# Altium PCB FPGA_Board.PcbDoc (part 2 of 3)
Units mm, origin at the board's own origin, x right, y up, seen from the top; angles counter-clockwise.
Board outline 130 x 90 mm, 4 copper layers (Component Side, Signal Layer 1, Signal Layer 2, Bottom Layer), stack 0.651 mm thick; 303 components, 175 nets, 968 pads, 775 vias.
Unrouted connection lines stored in the file: 193.
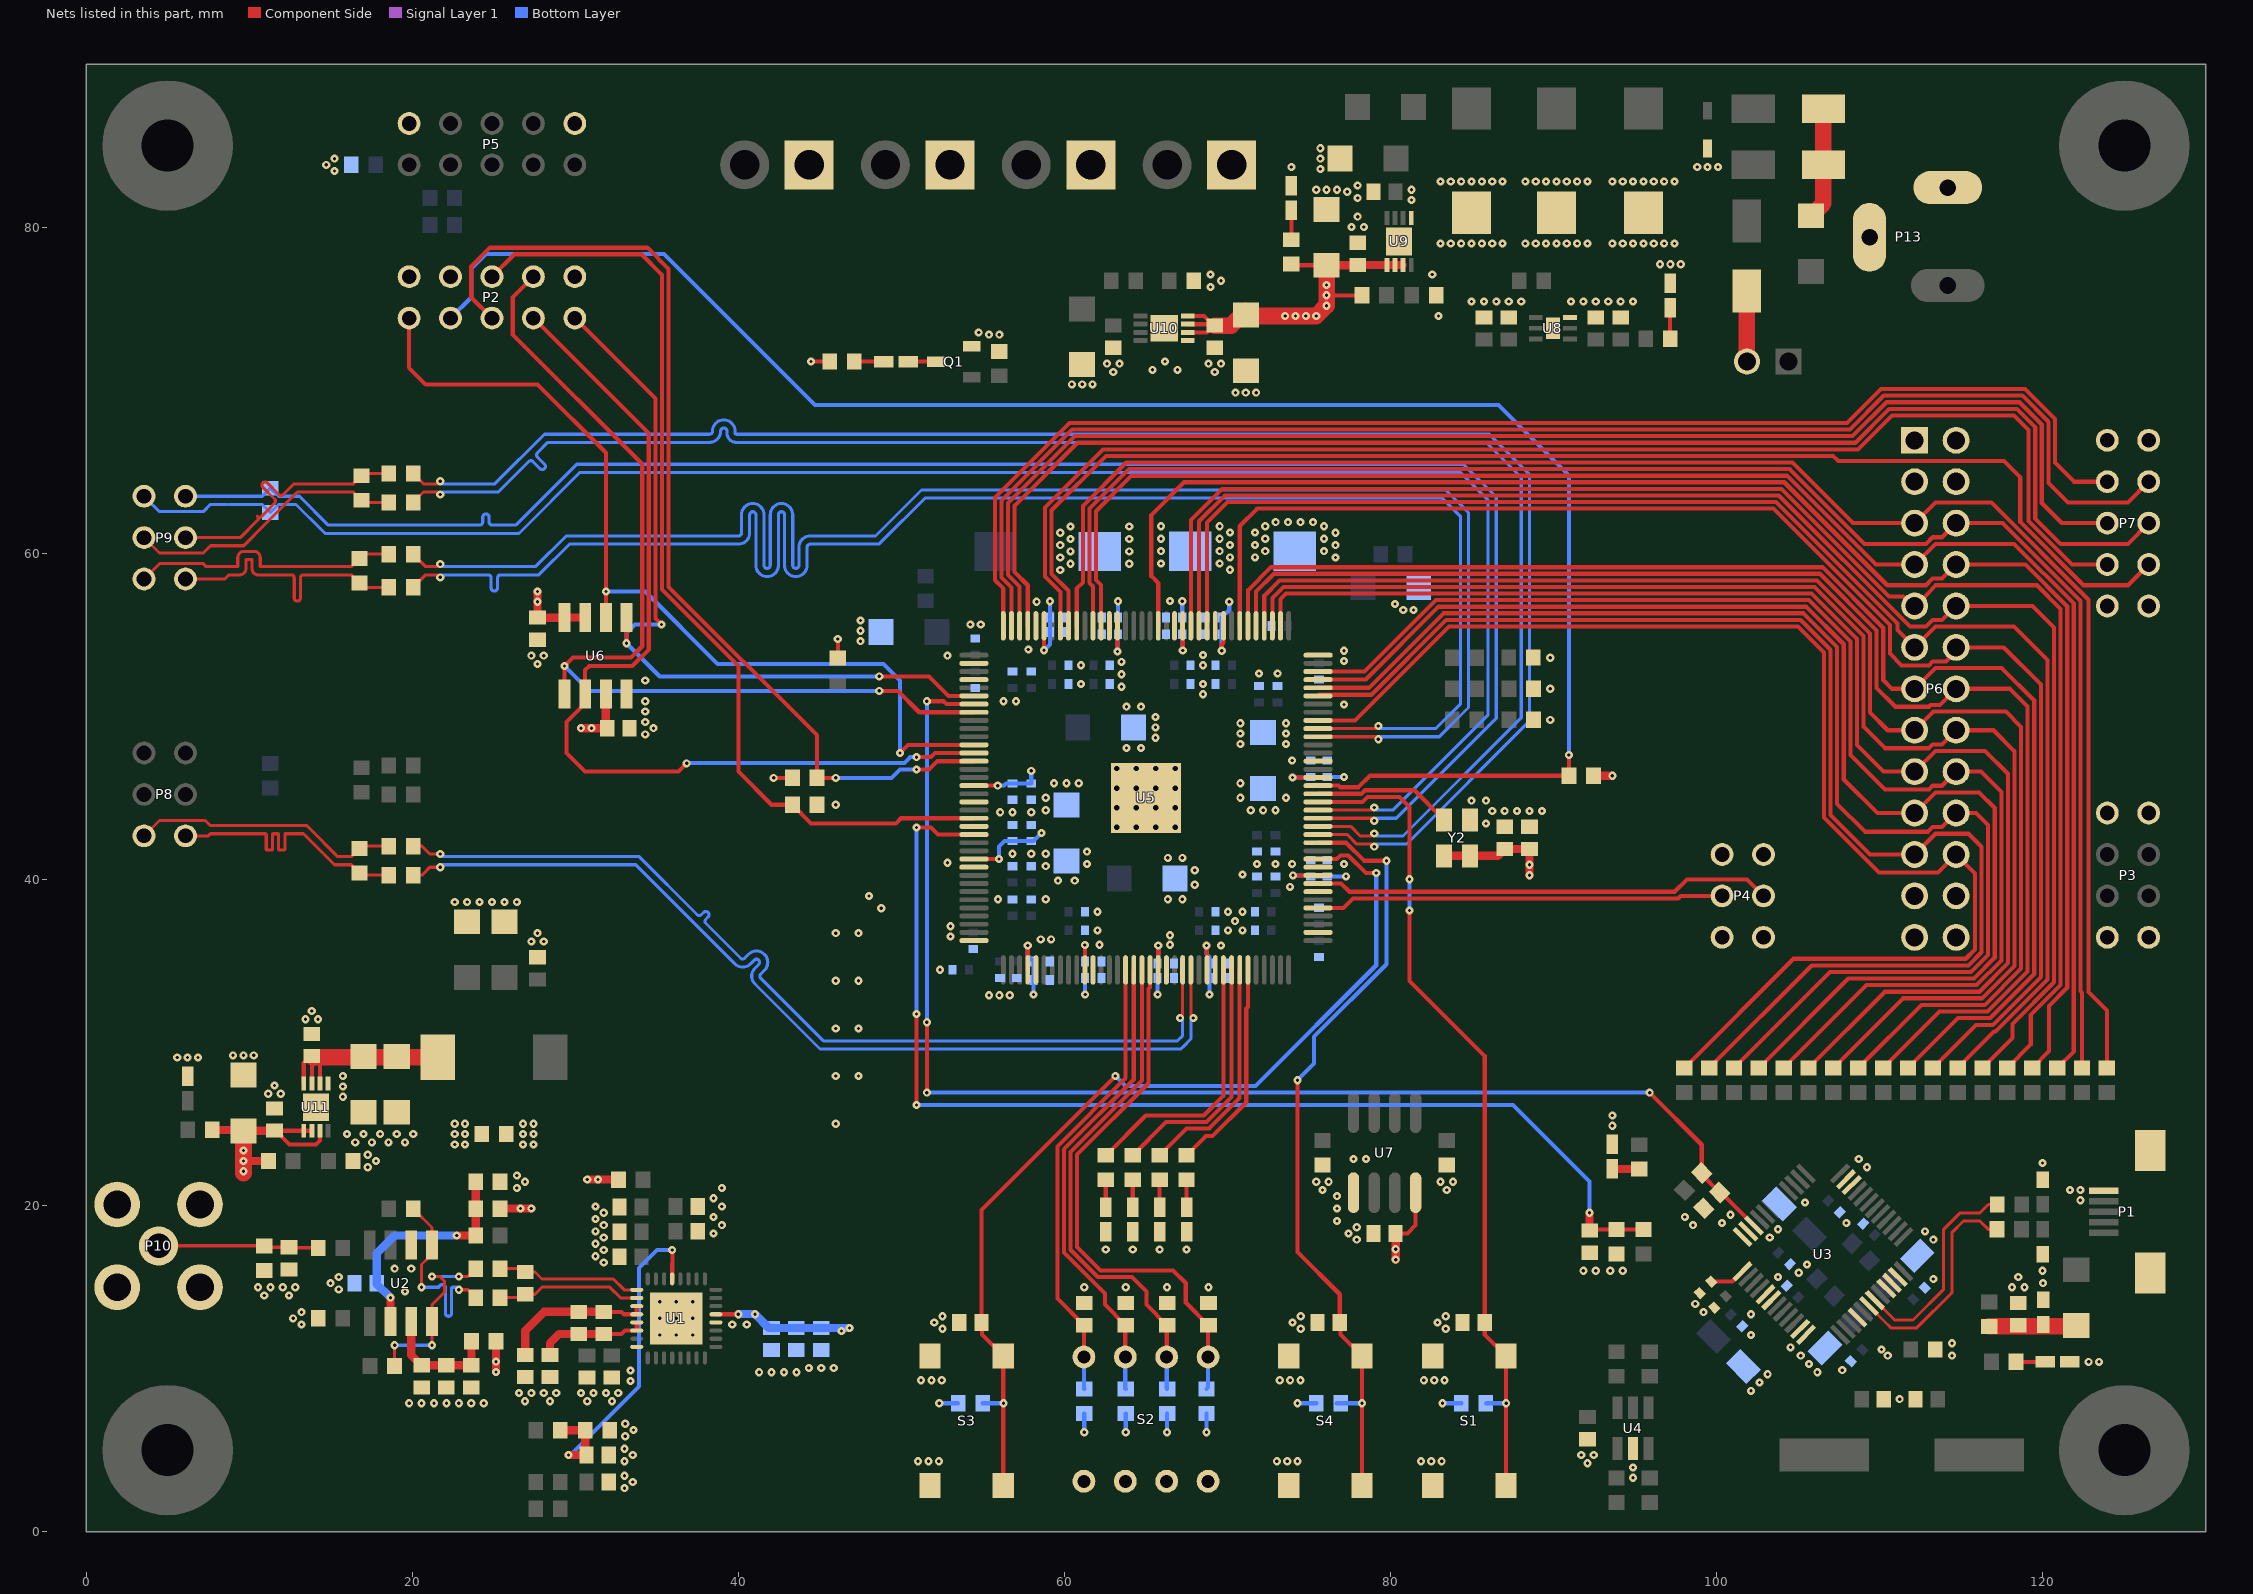
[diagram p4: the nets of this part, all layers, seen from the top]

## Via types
v1: diameter 0.5, hole 0.2, Component Side to Bottom Layer, 759 vias
v2: diameter 0.66, hole 0.33, Component Side to Bottom Layer, tented top, 16 vias

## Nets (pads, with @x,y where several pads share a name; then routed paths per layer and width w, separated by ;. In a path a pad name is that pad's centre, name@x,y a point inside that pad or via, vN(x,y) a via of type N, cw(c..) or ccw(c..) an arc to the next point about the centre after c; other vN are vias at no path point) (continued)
+3V3: C3.1 C5.1 C7.1 C43.2 C44.2 C51.1 C52.1 C53.2 C54.+ C55.2 C56.2 C57.2 C58.2 C59.2 C60.2 C61.2 C62.2 C63.2 C64.2 C65.2 C66.2 C67.2 C68.2 C69.2 C70.2 C71.2 C72.2 C73.2 C74.2 C75.2 C76.2 C77.2 C78.2 C79.2 C80.2 C131.2 C132.2 C133.2 C134.2 P2.4 P3.1 P3.2 P4.1 P4.2 P6.1 P6.2 P6.3 P6.4 P7.1 P7.2 R27.2 R31.2 R32.2 R33.2 R57.2 R58.2 R59.2 R60.2 R81.2 R82.2 R87.2 R88.2 R89.2 U1.21 U5.17 U5.26 U5.40 U5.47 U5.56 U5.62 U5.81 U5.93 U5.117 U5.122 U5.130 U5.139 U6.3 U6.7 U6.8 U7.8 U9.5 U9.6 U9.7 U10.2 U10.3 U10.4 Y2.1 Y2.4 | length 122.1
  Component Side w0.254: U1.21@38.62,13.331 v1(40.001,13.331) ; v1(42.164,46.228) R32.2@43.319,46.228 ; v1(44.45,71.755) R88.2@45.605,71.755 ; R33.2@46.101,53.582 v1(46.101,54.737) ; U5.26@54.45,41.25 v1(55.982,41.25) ; U5.17@54.45,45.75 v1(55.91,45.75) ; U5.40@57.75,34.45 v1(57.75,35.943) ; v1(58.75,54.051) U5.139@58.75,55.55 ; U5.47@61.25,34.45 v1(61.25,35.977) ; v1(63.25,53.979) U5.130@63.25,55.55 ; U5.56@65.75,34.45 v1(65.75,35.944) ; v1(67.25,54.042) U5.122@67.25,55.55 ; U10.2@67.564,73.549 68.73,73.549 69.14,73.959 C134.2@69.215,73.959 69.125,74.049 C134.2@69.05,74.049 ; U10.3@67.564,74.049 C134.2@69.05,74.049 ; U10.4@67.564,74.549 68.55,74.549 C134.2@69.05,74.049 ; v1(68.707,35.941) 68.707,35.56 68.75,35.517 U5.62@68.75,34.45 ; v1(69.643,54.022) 69.643,54.403 69.75,54.51 U5.117@69.75,55.55 ; R87.2@73.914,77.736 73.985,77.665 C132.2@76.073,77.665 ; v1(73.986,46.25) U5.93@75.55,46.25 ; v1(74.017,40.25) U5.81@75.55,40.25 ; v1(76.073,75.819) R89.2@78.244,75.819 ; C53.2@80.309,18.288 81.026,18.288 81.534,18.796 U7.8@81.534,20.791
  Component Side w0.508: v1(27.686,57.658) v1(27.686,57.023) C44.2@27.686,56.052 29.328,56.052 U6.8@29.337,56.061 U6.7@30.607,56.061 ; v1(30.353,49.276) v1(30.988,49.276) C43.2@31.959,49.276 31.877,49.358 U6.3@31.877,51.381 ; C132.2@76.073,77.665 77.964,77.665 C131.2@77.978,77.679 80.706,77.679 U9.7@80.714,77.671 ; v1(80.309,16.682) v1(80.309,17.317) C53.2@80.309,18.288 ; Y2.4@83.274,41.445 Y2.1@84.874,41.445 86.575,41.445 C52.1@86.995,41.865 C51.1@88.519,41.865 v1(88.519,40.894) v1(88.519,40.259) ; R31.2@92.444,46.355 v1(93.599,46.355)
  Component Side w1.016: C134.2@69.215,73.959 70.217,73.959 71.12,74.862 71.433,74.549 v1(73.533,74.549) v1(74.168,74.549) v1(74.803,74.549) v1(75.438,74.549) v1(76.073,75.184) v1(76.073,75.819) v1(76.073,76.454) C132.2@76.073,77.665
  Bottom Layer w0.254: v1(52.324,7.874) R81.2@53.479,7.874 ; v1(55.91,45.75) 56.291,45.75 56.427,45.886 C58.2@56.816,45.886 C57.2@57.959,45.886 v1(57.959,46.656) ; v1(55.982,41.25) 55.982,42.012 56.316,42.346 C60.2@56.816,42.346 C59.2@57.959,42.346 58.094,42.346 v1(58.594,42.846) ; v1(57.75,35.943) 57.75,35.316 C62.2@58.094,34.972 C61.2@58.094,33.829 v1(58.094,32.948) ; v1(58.75,54.051) 59.11,54.411 C80.2@59.11,55.165 C79.2@59.11,56.054 v1(59.11,57.062) ; v1(61.214,6.096) R57.2@61.214,7.251 ; v1(61.269,32.948) C63.2@61.269,33.956 C64.2@61.269,34.972 61.25,34.991 v1(61.25,35.977) v1@61.269,35.958 ; v1(63.25,53.979) 63.25,55.003 C77.2@63.285,55.038 C78.2@63.285,56.054 v1(63.285,57.062) ; v1(63.754,6.096) R58.2@63.754,7.251 ; v1(65.714,32.948) C65.2@65.714,33.956 C66.2@65.714,34.845 65.75,34.881 v1(65.75,35.944) ; v1(66.294,6.096) R59.2@66.294,7.251 ; v1(67.222,57.062) C76.2@67.222,56.054 C75.2@67.222,55.038 67.25,55.01 v1(67.25,54.042) ; v1(68.707,6.096) R60.2@68.707,7.251 ; v1(68.707,35.941) 68.707,35.433 68.889,35.251 C68.2@68.889,34.845 C67.2@68.889,33.956 v1(68.889,32.948) ; v1(69.643,54.022) 69.643,55.03 C74.2@69.635,55.038 C73.2@69.635,56.054 70.104,56.523 v1(70.104,57.023) ; v1(73.986,46.25) 75.071,46.25 C72.2@75.104,46.283 C71.2@76.12,46.283 77.128,46.283 v1(77.136,46.275) ; v1(74.017,40.25) 75.041,40.25 C70.2@75.104,40.187 C69.2@76.12,40.187 v1(77.271,40.187) ; v1(74.295,7.874) R82.2@75.45,7.874 ; v1(83.185,7.874) R27.2@84.34,7.874
  Bottom Layer w0.508: v1(40.001,13.331) 40.024,13.354 41.002,13.354 v1(41.021,13.335) 41.865,12.491 C7.1@42.037,12.491 C5.1@43.561,12.491 C3.1@45.085,12.491 46.146,12.491 v1(46.328,12.309) ; v1@46.328,12.491 v1(46.818,12.491)
  other v1: 58.848,44.243 71.421,44.243 72.183,44.243 72.945,44.243 58.848,45.005 70.786,45.005 73.58,45.005 59.356,45.894 60.118,45.894 60.88,45.894 70.786,45.894 76.628,59.737 71.679,59.751 72.314,60.132 75.916,60.132 76.628,60.499 71.679,60.513 72.314,60.894 75.916,60.894 76.628,61.261 71.679,61.275 72.314,61.656 75.916,61.656 72.949,61.91 73.711,61.91 74.473,61.91 75.235,61.91
+3V-A: C143.2 C144.2 L1.2 L2.2 R3.2 R94.2 R95.2 U11.5 U11.6 U11.7 | length 19.9
  Component Side w0.254: C143.2@11.557,24.593 11.632,24.593 C143.2@11.64,24.585 ; C143.2@11.565,24.585 C143.2@11.64,24.585 ; U11.6@13.847,24.585 U11.5@13.347,24.585 C143.2@11.64,24.585 ; U11.7@14.347,24.585 14.347,23.999 14.097,23.749 12.476,23.749 C143.2@11.64,24.585
  Component Side w0.508: R94.2@7.735,24.638 9.593,24.638 C144.2@9.638,24.593 ; v1(9.652,22.733) R95.2@11.188,22.733 ; C144.2@9.652,24.579 C144.2@9.638,24.593 ; C143.2@11.565,24.585 C143.2@11.557,24.593 C144.2@9.638,24.593 ; v1(25.134,9.791) v1(25.134,10.426) L2.2@25.134,11.684 ; R3.2@25.388,19.812 v1(26.646,19.812) v1(27.305,19.812) ; v1(30.734,21.59) v1(31.393,21.59) L1.2@32.651,21.59
  Component Side w1.016: v1@9.652,21.971 v1(9.652,22.098) v1(9.652,22.733) v1(9.652,23.368) C144.2@9.652,24.579
/RESET: C32.2 R15.1 U3.34 U5.7 | length 82
  Component Side w0.254: v1(51.562,26.924) v1(51.562,31.242) ; v1(51.562,50.927) 52.578,50.927 52.755,50.75 U5.7@54.45,50.75 ; v1(95.885,26.924) 99.082,23.727 R15.1@99.082,21.993 99.082,21.894 C32.2@100.176,20.801 100.262,20.801 U3.34@102.286,18.777
  Bottom Layer w0.254: v1(51.562,31.242) v1(51.562,50.927) ; v1@51.689,26.924 v1(95.885,26.924)
/RST: C42.1 R27.1 S1.1 S1.2 U5.90 | length 51.3
  Component Side w0.254: U5.90@75.55,44.75 78.278,44.75 78.59,45.062 80.541,45.062 81.153,44.45 v1(81.153,40.005) ; v1(81.153,38.1) 81.153,33.782 85.77,29.165 C42.1@85.77,12.827 85.77,12.091 S1.1@87.086,10.775 v1(87.086,7.874) S1.2@87.086,2.825
  Bottom Layer w0.254: v1(81.153,38.1) v1(81.153,40.005) ; R27.1@85.84,7.874 v1(87.086,7.874)
AGND: C1.2 C2.2 C4.2 C6.2 C8.2 C9.2 C10.1 C11.1 C12.2 C13.2 C16.1 C17.1 C19.1 C20.1 C21.2 C22.2 C140.1 C141.1 C142.1 C143.1 C144.1 D17.2 P10.2 P10.3 P10.4 P10.5 R4.1 R9.1 R10.1 R14.1 R96.1 R97.1 U1.8 U2.6 U11.1 U11.9
  other v1: 33.02,2.667 33.528,3.048 33.02,3.429 33.02,4.318 33.528,4.699 33.02,5.08 33.062,5.854 33.57,6.235 33.062,6.616 19.812,7.874 20.574,7.874 21.336,7.874 22.098,7.874 22.86,7.874 23.622,7.874 24.384,7.874 26.924,8.001 28.448,8.001 30.734,8.001 32.258,8.001 26.543,8.509 27.305,8.509 28.067,8.509 28.829,8.509 30.353,8.509 31.115,8.509 31.877,8.509 32.639,8.509 33.389,9.243 33.389,9.878 13.208,12.7 12.7,13.081 13.208,13.462 10.922,14.478 12.446,14.478 19.558,14.732 15.494,14.859 10.541,14.986 11.303,14.986 12.065,14.986 12.827,14.986 14.986,15.24 15.494,15.621 18.923,16.129 19.939,16.129 31.75,16.51 31.242,16.891 31.75,17.272 31.242,17.653 31.75,18.034 38.481,18.288 31.242,18.415 31.75,18.796 38.989,18.796 31.242,19.177 38.481,19.304 31.75,19.558 31.242,19.939 38.989,19.939 38.481,20.447 26.416,21.082 38.989,21.082 26.924,21.463 26.416,21.844 17.272,22.352 17.78,22.733 17.272,23.114 22.606,23.749 23.241,23.749 16.51,23.876 17.526,23.876 18.542,23.876 19.558,23.876 16.002,24.384 17.018,24.384 18.034,24.384 19.05,24.384 20.066,24.384 22.606,24.384 23.241,24.384 22.606,25.019 23.241,25.019 15.748,26.67 11.176,26.854 11.938,26.854 15.748,27.305 11.557,27.362 15.748,27.94 5.588,29.083 6.223,29.083 6.858,29.083 9.017,29.21 9.652,29.21 10.287,29.21 13.462,31.426 14.224,31.426 13.843,31.934
ASDI: P2.9 U5.6 U6.5 | length 48.2
  Component Side w0.254: P2.9@29.972,74.422 34.914,69.48 34.914,56.007 v1(35.295,55.626) ; v1(33.147,54.483) U6.5@33.147,56.061 ; v1(48.641,52.451) 51.689,52.451 52.89,51.25 U5.6@54.45,51.25
  Bottom Layer w0.254: v1(35.295,55.626) 33.655,55.626 33.147,55.118 v1(33.147,54.483) 35.179,52.451 v1(48.641,52.451)
BTN0: C49.1 R81.1 S3.1 S3.2 U5.83 | length 59.4
  Component Side w0.254: C49.1@54.909,12.827 54.909,19.73 v1(63.119,27.94) ; C49.1@54.934,12.827 54.934,12.091 S3.1@56.25,10.775 56.25,7.874 S3.2@56.25,2.825 ; U5.83@75.55,41.25 76.7,41.25 76.918,41.468 77.404,41.468 78.486,40.386 v1(79.121,40.386)
  Bottom Layer w0.254: R81.1@54.979,7.874 v1(56.261,7.874) ; v1(63.119,27.94) 63.731,27.328 71.715,27.328 79.121,34.734 v1(79.121,40.386)
BTN1: C50.1 R82.1 S4.1 S4.2 U5.85 | length 48.4
  Component Side w0.254: v1(74.295,27.686) 74.295,17.145 76.88,14.56 C50.1@76.88,12.827 ; U5.85@75.55,42.25 77.257,42.25 78.359,41.148 v1(79.756,41.148) ; C50.1@76.934,12.827 76.934,12.091 S4.1@78.25,10.775 v1(78.25,7.874) S4.2@78.25,2.825
  Bottom Layer w0.254: v1(74.295,27.686) 75.311,28.702 75.311,30.353 79.756,34.798 v1(79.756,41.148) ; R82.1@76.696,7.874 R82.1@76.95,7.874 v1(78.25,7.874)
CLK: U5.91 Y2.3 | length 8.6
  Component Side w0.254: U5.91@75.55,45.25 78.206,45.25 78.422,45.466 81.453,45.466 Y2.3@83.274,43.645
D_N: R16.2 U3.6 | length 13.5
  Component Side w0.19: U3.6@109.34,13.845 110.476,12.708 110.484,12.708 110.713,12.479 112.246,12.479 112.392,12.625 114.273,14.505 114.419,14.652 114.419,18.335 115.138,19.054 116.131,19.054 116.643,18.542 R16.2@117.188,18.542
D_P: R17.2 U3.7 | length 13.1
  Component Side w0.19: U3.7@109.693,14.198 110.684,13.208 110.691,13.208 110.92,12.979 112.039,12.979 113.919,14.859 113.919,18.542 114.681,19.304 114.931,19.554 116.143,19.554 116.655,20.066 R17.2@117.2,20.066
D_UART_RX: P4.3 U5.77 | length 25.1
  Component Side w0.254: U5.77@75.55,38.25 77.112,38.25 77.701,38.839 97.64,38.839 97.79,38.989 P4.3@100.33,38.989
D_UART_TX: P4.4 U5.80 | length 28.3
  Component Side w0.254: U5.80@75.55,39.75 76.963,39.75 77.47,39.243 97.409,39.243 98.171,40.005 101.854,40.005 P4.4@102.87,38.989
DATA: P2.7 U5.13 U6.2 | length 59.2
  Component Side w0.254: P2.7@27.432,74.422 34.51,67.344 34.51,54.102 33.494,53.086 30.861,53.086 30.607,52.832 U6.2@30.607,51.381 30.607,50.8 29.464,49.657 29.464,47.752 30.607,46.609 36.322,46.609 v1(36.83,47.117) ; v1(50.927,47.498) 51.816,47.498 52.068,47.75 U5.13@54.45,47.75
  Bottom Layer w0.254: v1(36.83,47.117) 36.853,47.14 50.188,47.14 50.546,47.498 v1(50.927,47.498)
DCLK: P2.1 U5.12 U6.6 | length 56.9
  Component Side w0.254: P2.1@19.812,74.422 19.812,71.374 20.828,70.358 27.686,70.358 31.877,66.167 v1(31.877,57.658) U6.6@31.877,56.061 ; v1(49.911,47.752) 50.409,48.25 U5.12@54.45,48.25
  Bottom Layer w0.254: v1(31.877,57.658) 34.29,57.658 38.735,53.213 48.895,53.213 49.911,52.197 v1(49.911,47.752)
DIP0: C45.2 R57.1 S2.2 U5.52 | length 28.2
  Component Side w0.254: S2.2@61.19,10.61 S2.2@61.19,10.71 61.19,12.631 C45.2@61.214,12.655 59.563,14.306 59.563,23.622 63.75,27.809 U5.52@63.75,34.45
  Bottom Layer w0.254: R57.1@61.214,8.751 61.19,8.775 61.19,10.61 S2.2@61.214,10.586
DIP1: C46.2 R58.1 S2.4 U5.53 | length 29.1
  Component Side w0.254: S2.4@63.73,10.61 S2.4@63.73,10.71 63.73,12.631 C46.2@63.754,12.655 62.484,13.925 62.484,14.605 59.967,17.122 59.967,23.455 64.25,27.738 U5.53@64.25,34.45
  Bottom Layer w0.254: S2.4@63.73,10.61 63.73,8.775 R58.1@63.754,8.751
DIP2: C47.2 R59.1 S2.6 U5.54 | length 31.2
  Component Side w0.254: U5.54@64.75,34.45 64.75,27.666 60.371,23.287 60.371,17.289 62.039,15.621 64.135,15.621 65.024,14.732 65.024,13.925 C47.2@66.294,12.655 66.27,12.631 S2.6@66.27,10.71 S2.6@66.27,10.61
  Bottom Layer w0.254: S2.6@66.27,10.61 66.27,8.775 R59.1@66.294,8.751
DIP3: C48.2 R60.1 S2.8 U5.55 | length 33.5
  Component Side w0.254: U5.55@65.25,34.45 65.25,33.373 65.154,33.277 65.154,27.499 60.775,23.12 60.775,17.457 62.207,16.025 66.652,16.025 67.437,15.24 67.437,14.052 C48.2@68.834,12.655 68.81,12.631 S2.8@68.81,10.71 S2.8@68.81,10.61
  Bottom Layer w0.254: R60.1@68.707,8.751 68.81,8.854 S2.8@68.81,10.61
EXT_In_N: P9.2 R72.1 U5.88 | length 112.5
  Component Side w0.19: U5.88@75.55,43.75 78.839,43.75 v1(78.994,43.595)
  Signal Layer 1 w0.19: v1@78.867,43.75 78.994,43.623 v1(78.994,43.595)
  Bottom Layer w0.19: P9.2@6.096,63.5 8.89,63.5 ; 8.763,63.496 10.803,63.496 R72.1@11.303,63.996 11.803,63.496 13.085,63.496 14.859,61.722 24.13,61.722 ccw(c24.13,61.917) 24.325,61.917 24.325,62.216 cw(c24.52,62.216) 24.52,62.411 cw(c24.52,62.216) 24.715,62.216 24.715,61.917 ccw(c24.91,61.917) 24.91,61.722 26.344,61.722 30.082,65.46 84.472,65.46 84.618,65.314 86.479,63.453 86.479,49.885 80.344,43.75 79.149,43.75 v1(78.994,43.595)
EXT_In_P: P9.1 R72.2 U5.89 | length 112.5
  Component Side w0.19: U5.89@75.55,44.25 78.839,44.25 v1(78.994,44.405)
  Bottom Layer w0.19: P9.1@3.556,63.5 4.501,62.555 7.183,62.555 7.628,63 8.683,63 ; 8.763,62.996 10.803,62.996 R72.2@11.303,62.496 11.803,62.996 12.878,62.996 14.505,61.368 14.652,61.222 26.551,61.222 26.697,61.368 30.29,64.96 84.265,64.96 85.979,63.246 85.979,50.092 80.137,44.25 79.149,44.25 v1(78.994,44.405)
EXT_Out0_N: R53.1 U5.86 | length 103.8
  Component Side w0.19: R53.1@20.054,64.897 20.693,64.258 21.59,64.258 21.717,64.385 v1(21.717,64.413) ; U5.86@75.55,42.75 76.545,42.75 77.343,42.75 77.929,42.164 78.839,42.164 v1(78.994,42.009)
  Bottom Layer w0.19: v1(21.717,64.413) 21.872,64.258 25.07,64.258 28.114,67.302 38.227,67.302 ccw(c38.227,67.492) 38.417,67.492 cw(c39.107,67.492) 39.107,68.182 cw(c39.107,67.492) 39.797,67.492 39.797,67.383 ccw(c39.878,67.383) 39.878,67.302 86.059,67.302 86.206,67.156 88.511,64.85 88.511,49.704 80.971,42.164 79.149,42.164 v1(78.994,42.009)
EXT_Out0_P: R47.1 U5.87 | length 103.8
  Component Side w0.19: R47.1@20.054,63.119 20.693,63.758 21.59,63.758 21.717,63.631 v1(21.717,63.603) ; U5.87@75.55,43.25 76.545,43.25 77.55,43.25 78.136,42.664 78.839,42.664 v1(78.994,42.819)
  Bottom Layer w0.19: v1(21.717,63.603) 21.872,63.758 25.277,63.758 26.86,65.341 26.998,65.479 27.136,65.617 cw(c27.274,65.479) 27.412,65.617 27.836,65.193 ccw(c27.974,65.331) 28.112,65.193 ccw(c27.974,65.331) 28.112,65.469 27.688,65.893 cw(c27.826,66.031) 27.688,66.169 28.321,66.802 38.227,66.802 ccw(c38.227,67.492) 38.917,67.492 cw(c39.107,67.492) 39.107,67.682 cw(c39.107,67.492) 39.297,67.492 39.297,67.383 ccw(c39.878,67.383) 39.878,66.802 85.852,66.802 88.011,64.643 88.011,49.911 80.764,42.664 79.149,42.664 v1(78.994,42.819)
EXT_Out0_R_N: P9.4 R50.1 R53.2 | length 17.2
  Component Side w0.19: P9.4@6.096,60.96 9.453,60.96 10.505,62.012 ; 10.505,62.281 cw(c10.371,62.146) 10.505,62.012 11.042,62.549 ; 11.042,62.549 11.557,63.064 ccw(c11.423,63.198) 11.557,63.333 10.842,64.048 cw(c10.976,64.182) 10.842,64.317 cw(c10.976,64.182) 11.111,64.317 11.828,63.6 ccw(c11.96,63.732) 12.092,63.6 12.751,64.258 16.391,64.258 R50.1@16.891,64.758 17.03,64.897 R53.2@18.554,64.897 R53.2@18.3,64.643
EXT_Out0_R_P: P9.3 R47.2 R50.2 | length 17.2
  Component Side w0.19: P9.3@3.556,60.96 4.501,60.015 7.183,60.015 7.628,60.46 9.66,60.46 10.993,61.793 12.958,63.758 14.079,63.758 16.391,63.758 R50.2@16.891,63.258 17.03,63.119 R47.2@18.554,63.119
EXT_Out1_N: R77.1 U5.99 | length 103.8
  Component Side w0.19: R77.1@20.054,57.912 20.82,58.678 21.562,58.678 v1(21.717,58.523) ; U5.99@75.55,49.25 79.093,49.25 v1(79.248,49.405)
  Bottom Layer w0.19: v1(21.717,58.523) 21.872,58.678 24.257,58.678 24.452,58.678 24.647,58.678 cw(c24.647,58.483) 24.842,58.483 24.842,57.877 ccw(c25.037,57.877) 25.037,57.682 ccw(c25.037,57.877) 25.232,57.877 25.232,58.483 cw(c25.427,58.483) 25.427,58.678 25.622,58.678 25.781,58.678 27.762,58.678 29.644,60.56 40.005,60.56 ccw(c40.005,61.25) 40.695,61.25 40.695,62.359 cw(c40.885,62.359) 40.885,62.549 cw(c40.885,62.359) 41.075,62.359 41.075,59.26 ccw(c41.765,59.26) 41.765,58.57 ccw(c41.765,59.26) 42.455,59.26 42.455,62.359 cw(c42.645,62.359) 42.645,62.549 cw(c42.645,62.359) 42.835,62.359 42.835,59.26 ccw(c43.525,59.26) 43.525,58.57 ccw(c43.525,59.26) 44.215,59.26 44.215,60.37 cw(c44.405,60.37) 44.405,60.56 48.622,60.56 48.768,60.706 51.443,63.381 83.177,63.381 84.277,62.281 84.277,50.749 82.778,49.25 79.403,49.25 v1(79.248,49.405)
EXT_Out1_P: R70.1 U5.98 | length 103.8
  Component Side w0.19: R70.1@20.054,59.944 20.82,59.178 21.562,59.178 v1(21.717,59.333) ; U5.98@75.55,48.75 79.093,48.75 v1(79.248,48.595)
  Bottom Layer w0.19: v1(21.717,59.333) 21.872,59.178 27.555,59.178 29.437,61.06 40.005,61.06 ccw(c40.005,61.25) 40.195,61.25 40.195,62.359 cw(c40.885,62.359) 40.885,63.049 cw(c40.885,62.359) 41.575,62.359 41.575,59.26 ccw(c41.765,59.26) 41.765,59.07 ccw(c41.765,59.26) 41.955,59.26 41.955,62.359 cw(c42.645,62.359) 42.645,63.049 cw(c42.645,62.359) 43.335,62.359 43.335,59.26 ccw(c43.525,59.26) 43.525,59.07 ccw(c43.525,59.26) 43.715,59.26 43.715,60.37 cw(c44.405,60.37) 44.405,61.06 48.414,61.06 51.236,63.881 83.384,63.881 83.666,63.6 84.631,62.634 84.777,62.488 84.777,50.542 82.985,48.75 79.403,48.75 v1(79.248,48.595)
EXT_Out1_R_N: P9.6 R74.1 R77.2 | length 17.3
  Component Side w0.19: P9.6@6.096,58.42 8.509,58.42 8.767,58.678 9.42,58.678 ccw(c9.42,59.06) 9.802,59.06 9.802,59.62 10.182,59.62 10.182,59.037 ccw(c10.541,59.037) 10.541,58.678 11.303,58.678 12.573,58.678 12.575,58.678 cw(c12.575,58.488) 12.765,58.488 12.765,57.259 ccw(c12.955,57.259) 12.955,57.069 ccw(c12.955,57.259) 13.145,57.259 13.145,58.488 cw(c13.335,58.488) 13.335,58.678 13.716,58.678 16.264,58.678 R74.1@16.764,58.178 17.03,57.912 R77.2@18.554,57.912
EXT_Out1_R_P: P9.5 R70.2 R74.2 | length 17.3
  Component Side w0.19: P9.5@3.556,58.42 4.501,59.365 7.183,59.365 7.37,59.178 9.302,59.178 9.302,59.738 cw(c9.684,59.738) 9.684,60.12 10.3,60.12 cw(c10.3,59.738) 10.682,59.738 10.682,59.178 16.264,59.178 R74.2@16.764,59.678 17.03,59.944 R70.2@18.554,59.944
Full_N: R76.1 U5.60 | length 58.9
  Component Side w0.19: R76.1@20.054,40.259 20.599,40.259 21.083,40.743 v1(21.717,40.743) ; U5.60@67.75,34.45 67.75,31.651 v1(67.905,31.496)
  Bottom Layer w0.19: v1(21.717,40.743) 21.872,40.898 33.706,40.898 35.46,39.143 39.778,34.825 ccw(c40.266,35.313) 40.754,34.825 40.98,35.052 cw(c41.115,34.917) 41.249,35.052 ; 41.25,35.051 cw(c41.115,34.917) 41.305,34.917 cw(c41.115,34.917) 41.249,34.783 41.023,34.557 ccw(c41.511,34.069) 41.023,33.581 45.005,29.599 67.136,29.599 67.283,29.745 67.75,30.213 67.75,31.341 v1(67.905,31.496)
Full_P: R69.1 U5.59 | length 58.9
  Component Side w0.19: R69.1@20.054,42.037 20.599,42.037 21.083,41.553 v1(21.717,41.553) ; v1(67.095,31.496) 67.25,31.651 U5.59@67.25,34.45
  Bottom Layer w0.19: v1(21.717,41.553) 21.872,41.398 33.889,41.398 33.901,41.41 37.465,37.846 ccw(c37.603,37.984) 37.741,37.846 37.87,37.975 cw(c38.008,37.837) 38.146,37.975 cw(c38.008,37.837) 38.146,37.699 38.017,37.57 ccw(c38.154,37.432) 38.017,37.294 38.418,36.893 40.132,35.179 ccw(c40.266,35.313) 40.401,35.179 40.627,35.405 cw(c41.115,34.917) 41.603,35.405 cw(c41.115,34.917) 41.805,34.917 cw(c41.115,34.917) 41.603,34.429 41.376,34.203 ccw(c41.511,34.069) 41.377,33.934 45.212,30.099 66.929,30.099 67.25,30.42 67.25,31.341 v1(67.095,31.496)
Full_R_N: P8.6 R73.1 R76.2 | length 17.4
  Component Side w0.19: P8.6@6.096,42.672 7.493,42.672 7.62,42.799 10.477,42.799 10.667,42.799 10.99,42.799 cw(c10.99,42.742) 11.047,42.742 11.047,41.856 ccw(c11.104,41.856) 11.104,41.799 11.37,41.799 ccw(c11.37,41.856) 11.427,41.856 11.427,42.742 cw(c11.484,42.742) 11.484,42.799 11.75,42.799 cw(c11.75,42.742) 11.807,42.742 11.807,41.856 ccw(c11.864,41.856) 11.864,41.799 12.13,41.799 ccw(c12.13,41.856) 12.187,41.856 12.187,42.799 12.192,42.799 13.335,42.799 15.236,40.898 16.264,40.898 R73.1@16.764,40.398 16.903,40.259 R76.2@18.554,40.259
Full_R_P: P8.5 R69.2 R73.2 | length 16.6
  Component Side w0.19: P8.5@3.556,42.672 4.501,43.617 7.31,43.617 7.628,43.299 13.542,43.299 13.669,43.172 15.443,41.398 16.264,41.398 R73.2@16.764,41.898 16.903,42.037 R69.2@18.554,42.037
GND: C3.2 C5.2 C7.2 C23.2 C24.1 C25.2 C26.1 C27.1 C28.2 C29.1 C30.2 C31.1 C32.1 C33.1 C34.1 C35.1 C36.1 C37.1 C38.1 C39.1 C40.1 C41.1 C42.2 C43.1 C44.1 C45.1 C46.1 C47.1 C48.1 C49.2 C50.2 C51.2 C52.2 C53.1 C54.- C55.1 C56.1 C57.1 C58.1 C59.1 C60.1 C61.1 C62.1 C63.1 C64.1 C65.1 C66.1 C67.1 C68.1 C69.1 C70.1 C71.1 C72.1 C73.1 C74.1 C75.1 C76.1 C77.1 C78.1 C79.1 C80.1 C81.1 C82.1 C83.1 C84.1 C85.1 C86.1 C87.1 C88.1 C89.1 C90.1 C91.1 C92.1 C93.1 C94.1 C95.1 C96.1 C97.1 C98.1 C99.1 C100.1 C101.1 C102.1 C103.1 C104.1 C105.1 C106.1 C107.1 C108.1 C109.1 C110.1 C111.- C112.1 C113.1 C114.1 C115.1 C116.1 C117.1 C118.1 C119.1 C120.1 C121.1 C122.- C123.- C124.- C125.1 C126.1 C127.1 C128.1 C129.1 C130.1 C131.1 C132.1 C133.1 C134.1 C135.1 C136.1 C137.1 C138.1 C139.1 D1.1 D2.1 D3.1 D4.2 D5.2 D6.2 D7.2 D8.2 D9.2 D12.1 D13.2 D15.2 P1.5 P2.2 P2.10 P3.7 P3.8 P4.5 P4.6 P5.2 P5.10 P6.23 P6.24 P6.25 P6.26 P7.9 P7.10 P11.1 P12.1 P13.2 P13.3 P14.1 P15.1 Q1.2 R18.1 R26.1 R34.1 R35.1 R36.1 R37.2 R40.2 R83.1 R84.1 R91.1 R92.1 R93.1 R97.2 S1.3 S1.4 S2.1 S2.3 S2.5 S2.7 S3.3 S3.4 S4.3 S4.4 U1.20 U1.33 U3.4 U3.9 U3.10 U3.11 U3.22 U3.23 U3.35 U3.36 U3.41 U3.42 U3.47 U3.48 U4.2 U5.2 U5.4 U5.19 U5.22 U5.27 U5.36 U5.41 U5.48 U5.57 U5.63 U5.74 U5.79 U5.82 U5.95 U5.108 U5.118 U5.123 U5.131 U5.140 U5.145 U6.4 U7.5 U8.3 U8.7 U9.1 U9.9 U10.1 U10.9 Y2.2
  other v1: 94.869,3.302 94.869,3.937 92.075,4.191 51.025,4.318 51.66,4.318 52.295,4.318 73.025,4.318 73.66,4.318 74.295,4.318 81.861,4.318 82.496,4.318 83.131,4.318 91.694,4.699 92.456,4.699 111.219,8.128 102.108,8.636 102.616,9.144 51.205,9.282 51.84,9.282 52.475,9.282 73.205,9.282 73.84,9.282 74.475,9.282 82.041,9.282 82.676,9.282 83.311,9.282 103.124,9.652 41.275,9.779 42.037,9.779 42.799,9.779 43.561,9.779 106.172,9.779 107.696,9.906 44.323,10.033 45.085,10.033 45.847,10.033 105.664,10.287 122.809,10.414 123.444,10.414 105.156,10.795 110.49,10.795 114.427,10.795 110.109,11.176 104.521,11.303 114.427,11.557 35.179,12.065 36.195,12.065 37.211,12.065 102.108,12.065 52.521,12.446 74.492,12.446 83.382,12.446 39.624,12.7 40.513,12.7 52.013,12.827 73.984,12.827 82.874,12.827 35.179,13.081 36.195,13.081 37.211,13.081 52.521,13.208 74.492,13.208 83.382,13.208 102.108,13.335 99.187,13.462 98.679,13.97 35.179,14.097 36.195,14.097 37.211,14.097 61.214,14.986 63.754,14.986 66.294,14.986 68.834,14.986 118.11,14.986 118.872,14.986 120.015,15.24 113.284,15.494 103.759,15.621 118.491,15.621 105.029,15.875 91.821,16.002 92.583,16.002 93.472,16.002 94.234,16.002 119.982,16.002 105.537,16.383 62.535,17.304 64.186,17.304 65.837,17.304 67.488,17.304 77.921,17.907 113.284,17.907 103.251,18.034 77.413,18.288 112.776,18.415 103.759,18.542 77.921,18.669 98.552,18.796 100.33,18.923 107.95,18.923 76.708,19.05 98.044,19.304 100.838,19.431 76.708,19.812 105.41,20.193 122.301,20.32 76.708,20.574 75.819,20.955 83.439,20.955 121.666,20.955 122.301,20.955 75.438,21.463 76.2,21.463 83.058,21.463 83.82,21.463 109.22,22.352 119.982,22.606 77.724,22.86 78.486,22.86 108.712,22.86 26.797,23.749 27.432,23.749 26.797,24.384 27.432,24.384 93.599,24.892 26.797,25.019 27.432,25.019 45.974,25.019 93.599,25.527 45.974,27.94 47.371,27.94 45.974,30.861 47.371,30.861 55.372,32.893 56.007,32.893 56.642,32.893 45.974,33.782 47.371,33.782 52.371,34.464 69.596,35.941 62.15,35.988 66.468,35.988 27.305,36.195 28.067,36.195 58.547,36.322 59.182,36.322 53.006,36.496 66.472,36.576 27.686,36.703 45.974,36.703 47.371,36.703 62.023,36.877 70.024,36.877 70.913,36.877 53.006,37.131 70.46,37.44 62.023,38.02 70.024,38.02 70.913,38.02 48.768,38.227 22.606,38.608 23.368,38.608 24.13,38.608 24.892,38.608 25.654,38.608 26.416,38.608 55.927,38.782 58.848,38.782 66.341,38.782 67.23,38.782 48.006,38.989 73.834,39.544 67.992,39.671 59.61,39.925 60.626,39.925 70.913,40.306 67.992,40.56 58.848,40.814 61.388,40.941 71.802,40.941 72.945,40.941 73.961,40.941 77.136,40.941 52.832,41.021 66.341,41.322 67.23,41.322 56.816,41.576 57.959,41.576 58.848,41.576 61.388,41.703 85.852,43.434 56.054,44.116 56.816,44.116 57.959,44.116 86.233,44.196 86.995,44.196 87.757,44.196 88.519,44.196 89.281,44.196 45.974,44.577 84.963,44.831 85.852,44.831 73.961,47.291 63.801,48.053 64.69,48.053 70.786,48.307 73.58,48.307 65.579,48.688 34.29,48.895 70.786,48.942 73.58,48.942 34.798,49.276 65.579,49.323 70.786,49.577 73.58,49.577 34.29,49.657 89.789,49.784 65.579,49.958 34.29,50.292 63.801,50.593 64.69,50.593 77.136,50.72 34.29,50.927 56.261,50.927 57.023,50.927 68.5,51.355 89.789,51.689 63.5,51.816 61.007,51.99 68.5,51.99 34.29,52.197 63.5,52.578 71.929,52.625 73.072,52.625 61.007,53.133 68.5,53.133 27.686,53.213 63.5,53.34 77.136,53.387 89.789,53.594 27.305,53.721 28.067,53.721 52.832,53.721 68.5,53.768 77.136,54.022 57.785,54.102 47.498,54.61 47.498,55.245 54.229,55.626 54.864,55.626 47.498,55.88 80.772,56.515 81.407,56.515 80.264,56.896 58.293,57.023 66.468,57.07 59.737,58.975 70.151,58.989 60.372,59.356 63.974,59.356 65.914,59.37 69.516,59.37 59.737,59.737 70.151,59.751 60.372,60.118 63.974,60.118 65.914,60.132 69.516,60.132 59.737,60.499 70.151,60.513 60.372,60.88 63.974,60.88 65.914,60.894 69.516,60.894 59.737,61.261 70.151,61.275 60.372,61.642 63.974,61.642 65.914,61.656 69.516,61.656 70.485,69.85 71.12,69.85 71.755,69.85 60.452,70.358 61.087,70.358 61.722,70.358 62.992,71.12 69.215,71.12 65.405,71.247 66.929,71.247 62.611,71.628 63.373,71.628 68.834,71.628 69.596,71.628 66.167,71.755 55.372,73.406 56.007,73.406 54.737,73.533 82.931,74.549 84.963,75.438 85.725,75.438 86.487,75.438 87.249,75.438 88.011,75.438 91.059,75.438 91.821,75.438 92.583,75.438 93.345,75.438 94.107,75.438 94.869,75.438 68.961,76.327 69.596,76.708 68.961,77.089 82.55,77.089 96.52,77.724 97.155,77.724 97.79,77.724 83.058,78.994 83.693,78.994 84.328,78.994 84.963,78.994 85.598,78.994 86.233,78.994 86.868,78.994 88.265,78.994 88.9,78.994 89.535,78.994 90.17,78.994 90.805,78.994 91.44,78.994 92.075,78.994 93.599,78.994 94.234,78.994 94.869,78.994 95.504,78.994 96.139,78.994 96.774,78.994 97.409,78.994 77.597,80.01 78.359,80.01 77.978,80.645 81.28,81.661 77.978,81.788 77.343,82.169 75.438,82.296 76.073,82.296 76.708,82.296 81.28,82.296 77.978,82.55 83.058,82.804 83.693,82.804 84.328,82.804 84.963,82.804 85.598,82.804 86.233,82.804 86.868,82.804 88.265,82.804 88.9,82.804 89.535,82.804 90.17,82.804 90.805,82.804 91.44,82.804 92.075,82.804 93.599,82.804 94.234,82.804 94.869,82.804 95.504,82.804 96.139,82.804 96.774,82.804 97.409,82.804 15.24,83.439 75.692,83.566 73.914,83.693 98.806,83.693 99.441,83.693 100.076,83.693 14.732,83.82 15.24,84.201 75.692,84.201 75.692,84.836
  other v2: 63.2,43.2 64.4,43.2 65.6,43.2 66.8,43.2 63.2,44.4 64.4,44.4 65.6,44.4 66.8,44.4 63.2,45.6 64.4,45.6 65.6,45.6 66.8,45.6 63.2,46.8 64.4,46.8 65.6,46.8 66.8,46.8
In_N: R7.1 R8.2 U2.5 | length 12.7
  Component Side w0.19: R8.2@20.054,19.812 21.209,18.657 U2.5@21.209,17.58 20.944,17.315 20.944,16.753 20.57,16.379 v1(20.57,14.99) ; v1(22.86,14.835) 23.404,14.835 R7.1@23.888,14.351
  Bottom Layer w0.19: v1(20.57,14.99) 21.463,14.99 21.653,14.99 cw(c21.808,14.99) 21.808,15.145 21.878,15.145 cw(c21.878,14.99) 22.033,14.99 22.033,13.398 ccw(c22.223,13.398) 22.223,13.208 ccw(c22.223,13.398) 22.413,13.398 22.413,14.924 cw(c22.479,14.924) 22.479,14.99 22.705,14.99 v1(22.86,14.835)
In_P: R1.2 R5.1 U2.4 | length 11.6
  Component Side w0.19: R1.2@18.911,10.16 18.923,10.172 v1(18.923,11.43) ; v1(21.209,11.43) U2.4@21.209,12.9 21.209,13.909 21.971,14.671 21.971,15.367 21.693,15.645 v1(21.209,15.645) ; v1(22.86,15.645) 23.404,15.645 R5.1@23.888,16.129
  Bottom Layer w0.19: v1(18.923,11.43) v1(21.209,11.43) ; v1(21.209,15.645) v1(22.86,15.645)
InR_N: C14.1 R7.2 U1.2 | length 8.9
  Component Side w0.19: R7.2@25.388,14.351 26.715,14.351 C14.1@26.924,14.56 27.529,14.56 27.963,14.994 32.123,14.994 32.786,14.331 U1.2@33.77,14.331
InR_P: C14.2 R5.2 U1.1 | length 8.9
  Component Side w0.19: R5.2@25.388,16.129 26.715,16.129 C14.2@26.924,15.92 27.529,15.92 27.955,15.494 32.33,15.494 32.993,14.831 U1.1@33.77,14.831
IO0: P7.3 U5.144 | length 83
  Component Side w0.254: U5.144@56.25,55.55 56.25,57.827 55.731,58.346 55.731,63.414 60.307,67.99 107.996,67.99 110.075,70.069 118.906,70.069 120.742,68.233 120.742,65.567 121.92,64.389 P7.3@123.952,64.389
IO1: P7.4 U5.143 | length 86.4
  Component Side w0.254: U5.143@56.75,55.55 56.75,57.898 56.135,58.513 56.135,63.247 60.474,67.586 108.163,67.586 110.242,69.665 118.739,69.665 120.338,68.066 120.338,64.32 121.539,63.119 125.222,63.119 P7.4@126.492,64.389
IO2: P7.5 U5.142 | length 83.7
  Component Side w0.254: U5.142@57.25,55.55 57.25,57.97 56.539,58.681 56.539,63.079 60.642,67.182 108.33,67.182 110.409,69.261 118.572,69.261 119.934,67.899 119.934,63.073 121.158,61.849 P7.5@123.952,61.849
IO3: P7.6 U5.141 | length 86.9
  Component Side w0.254: U5.141@57.75,55.55 57.75,58.041 56.943,58.848 56.943,62.912 60.809,66.778 108.498,66.778 110.577,68.857 118.404,68.857 119.53,67.731 119.53,62.142 121.093,60.579 125.222,60.579 P7.6@126.492,61.849
IO4: P7.7 U5.137 | length 82.2
  Component Side w0.254: U5.137@59.75,55.55 59.75,57.629 58.806,58.573 58.806,62.806 62.374,66.374 108.665,66.374 110.744,68.453 118.237,68.453 119.126,67.564 119.126,61.975 121.792,59.309 P7.7@123.952,59.309
IO5: P7.8 U5.136 | length 81.6
  Component Side w0.254: U5.136@60.25,55.55 60.25,57.7 59.21,58.74 59.21,62.639 62.541,65.97 107.138,65.97 107.455,65.652 117.609,65.652 118.618,64.643 118.618,61.912 122.491,58.039 125.222,58.039 P7.8@126.492,59.309
IO6: P6.5 R80.1 U5.135 | length 104
  Component Side w0.254: U5.135@60.75,55.55 60.75,57.829 61.134,58.213 61.134,62.912 63.788,65.566 104.642,65.566 108.359,61.849 P6.5@112.141,61.849 113.411,63.119 116.839,63.119 122.809,57.149 122.809,33.086 123.927,31.969 R80.1@123.927,28.436
IO7: P6.6 R79.1 U5.133 | length 102.1
  Component Side w0.254: U5.133@61.75,55.55 61.75,57.978 61.538,58.19 61.538,62.745 63.955,65.162 104.475,65.162 109.058,60.579 112.84,60.579 113.244,60.983 113.815,60.983 P6.6@114.681,61.849 117.538,61.849 122.301,57.086 122.301,33.15 122.403,33.048 R79.1@122.403,28.436
IO8: P6.7 R78.1 U5.132 | length 101.2
  Component Side w0.254: U5.132@62.25,55.55 62.25,58.049 61.942,58.357 61.942,62.577 64.123,64.758 104.308,64.758 109.757,59.309 P6.7@112.141,59.309 113.411,60.579 118.237,60.579 121.897,56.919 121.897,29.454 R78.1@120.879,28.436
IO9: P6.8 R75.1 U5.125 | length 97.4
  Component Side w0.254: U5.125@65.75,55.55 65.75,58.169 65.325,58.594 65.325,62.357 67.322,64.354 104.14,64.354 110.455,58.039 112.84,58.039 113.244,58.443 113.815,58.443 P6.8@114.681,59.309 118.935,59.309 121.493,56.751 121.493,33.357 120.383,32.247 120.383,29.464 R75.1@119.355,28.436
IO10: P6.9 R71.1 U5.121 | length 94.4
  Component Side w0.254: U5.121@67.75,55.55 67.75,62.035 69.665,63.95 103.973,63.95 110.568,57.355 111.428,57.355 112.078,56.706 112.141,56.642 112.204,56.712 113.411,58.039 119.634,58.039 121.089,56.584 121.089,33.524 119.255,31.69 119.255,29.868 R71.1@117.823,28.436
IO11: P6.10 R68.1 U5.120 | length 92.9
  Component Side w0.254: U5.120@68.25,55.55 68.25,61.963 69.833,63.546 103.806,63.546 111.853,55.499 112.84,55.499 113.244,55.903 113.815,55.903 P6.10@114.681,56.769 119.357,56.769 120.685,55.441 120.685,33.692 118.135,31.142 118.135,30.272 R68.1@116.299,28.436 R68.1@116.445,28.436
IO12: P6.11 R67.1 U5.119 | length 91
  Component Side w0.254: U5.119@68.75,55.55 68.75,61.892 70,63.142 103.638,63.142 111.076,55.704 111.076,55.294 P6.11@112.141,54.229 113.411,55.499 118.237,55.499 120.281,53.455 120.281,33.859 117.098,30.676 117.015,30.676 R67.1@114.775,28.436
IO13: P6.12 R66.1 U5.115 | length 89.1
  Component Side w0.254: U5.115@70.75,55.55 70.748,55.552 70.748,61.661 71.825,62.738 103.471,62.738 110.617,55.592 110.617,53.848 111.338,53.127 113.008,53.127 113.244,53.363 114.069,53.363 114.681,53.975 P6.12@114.681,54.229 117.602,54.229 119.877,51.954 119.877,34.026 116.931,31.08 115.895,31.08 R66.1@113.251,28.436
IO14: P6.13 R61.1 U5.114 | length 84.2
  Component Side w0.254: U5.114@71.25,55.55 71.25,57.749 71.275,57.749 72.673,59.147 106.491,59.147 110.213,55.425 110.213,52.22 110.744,51.689 P6.13@112.141,51.689 113.411,52.959 117.475,52.959 119.473,50.961 119.473,34.194 116.775,31.496 114.787,31.496 R61.1@111.727,28.436
IO15: P6.14 R56.1 U5.113 | length 83.8
  Component Side w0.254: U5.113@71.75,55.55 71.75,57.653 72.84,58.743 106.323,58.743 109.809,55.257 109.809,51.735 110.957,50.587 113.008,50.587 113.117,50.696 113.688,50.696 P6.14@114.681,51.689 117.983,51.689 119.069,50.603 119.069,34.361 116.608,31.9 113.667,31.9 R56.1@110.203,28.436
IO16: P6.15 R55.1 U5.112 | length 83.5
  Component Side w0.254: U5.112@72.25,55.55 72.25,57.391 73.198,58.339 106.156,58.339 109.405,55.09 109.405,50.234 110.49,49.149 P6.15@112.141,49.149 113.284,50.292 117.729,50.292 118.665,49.356 118.665,34.528 116.441,32.304 112.547,32.304 R55.1@108.679,28.436
IO17: P6.16 R54.1 U5.111 | length 82.7
  Component Side w0.254: U5.111@72.75,55.55 72.75,57.256 73.429,57.935 105.989,57.935 109.001,54.922 109.001,49.368 110.322,48.047 113.008,48.047 113.244,48.283 113.815,48.283 P6.16@114.681,49.149 116.967,49.149 118.261,47.855 118.261,34.696 116.273,32.708 111.427,32.708 R54.1@107.155,28.436
IO18: P6.17 R51.1 U5.110 | length 82.3
  Component Side w0.254: U5.110@73.25,55.55 73.25,57.185 73.596,57.531 105.821,57.531 108.597,54.755 108.597,48.248 110.236,46.609 P6.17@112.141,46.609 113.411,47.879 116.459,47.879 117.857,46.481 117.857,34.863 116.106,33.112 110.307,33.112 R51.1@105.631,28.436
IO19: P6.18 R45.1 U5.106 | length 80
  Component Side w0.254: U5.106@75.55,52.75 78.404,52.75 82.781,57.127 105.654,57.127 108.193,54.588 108.193,47.636 110.322,45.507 113.008,45.507 113.244,45.743 113.815,45.743 P6.18@114.681,46.609 116.205,46.609 117.453,45.361 117.453,35.03 115.939,33.516 109.187,33.516 R45.1@104.107,28.436
IO20: P6.19 R44.1 U5.105 | length 80.8
  Component Side w0.254: U5.105@75.55,52.25 78.475,52.25 82.948,56.723 105.486,56.723 107.789,54.42 107.789,46.135 109.855,44.069 P6.19@112.141,44.069 113.411,45.339 116.078,45.339 117.049,44.368 117.049,35.198 115.771,33.92 108.067,33.92 R44.1@102.583,28.436
IO21: P6.20 R43.1 U5.104 | length 81.4
  Component Side w0.254: U5.104@75.55,51.75 78.674,51.75 83.243,56.319 105.319,56.319 107.385,54.253 107.385,44.634 109.093,42.926 112.967,42.926 113.244,43.203 113.815,43.203 P6.20@114.681,44.069 115.906,44.069 116.645,43.33 116.645,35.365 115.604,34.324 106.947,34.324 R43.1@101.059,28.436
IO22: P6.21 R42.1 U5.103 | length 81.5
  Component Side w0.254: U5.103@75.55,51.25 75.623,51.323 78.818,51.323 83.41,55.915 105.152,55.915 106.981,54.086 106.981,43.958 109.41,41.529 P6.21@112.141,41.529 113.411,42.799 115.443,42.799 116.241,42.001 116.241,35.532 115.437,34.728 105.827,34.728 R42.1@99.535,28.436
IO23: P6.22 R41.1 U5.100 | length 81.3
  Component Side w0.254: U5.100@75.55,49.75 77.817,49.75 83.578,55.511 104.984,55.511 106.577,53.918 106.577,43.791 109.941,40.427 113.579,40.427 P6.22@114.681,41.529 115.837,40.373 115.837,35.7 115.269,35.132 104.707,35.132 R41.1@98.011,28.436
LED0: R62.1 U5.64 | length 16.4
  Component Side w0.254: R62.1@62.535,23.077 64.985,25.527 68.541,25.527 69.75,26.736 U5.64@69.75,34.45
LED1: R63.1 U5.65 | length 15.3
  Component Side w0.254: R63.1@64.186,23.077 66.232,25.123 68.709,25.123 70.25,26.664 U5.65@70.25,34.45
LED2: R64.1 U5.66 | length 14.2
  Component Side w0.254: R64.1@65.837,23.077 67.479,24.719 68.876,24.719 70.744,26.587 70.744,34.444 U5.66@70.75,34.45
LED3: R65.1 U5.67 | length 13.2
  Component Side w0.254: R65.1@67.488,23.077 68.668,24.257 69.088,24.257 71.148,26.317 71.148,32.084 71.25,32.186 U5.67@71.25,34.45
MODE: C21.1 R11.1 R14.2 U1.29 | length 21.8
  Component Side w0.254: v1(35.941,17.272) 35.96,17.253 35.96,16.419 35.945,16.404 U1.29@35.945,15.506
  Component Side w0.508: R11.1@29.071,6.223 R14.2@30.619,6.223 30.619,4.769 C21.1@30.689,4.699 v1(29.591,4.699)
  Bottom Layer w0.254: v1(29.591,4.699) 29.701,4.699 33.916,8.914 33.916,10.096 33.909,10.103 33.909,16.174 35.007,17.272 v1(35.941,17.272)
nCE: P2.6 R37.1 U5.21 | length 59.8
  Component Side w0.254: P2.6@24.892,76.962 26.266,78.336 34.059,78.336 35.318,77.077 35.318,57.773 40.005,53.086 40.005,46.609 42.037,44.577 R37.1@43.319,44.577 44.462,43.434 49.657,43.434 49.973,43.75 U5.21@54.45,43.75
nCONF_DOWN: P2.3 R31.1 U5.92 | length 111
  Component Side w0.254: U5.92@75.55,45.75 U5.92@75.55,45.75 76.805,45.75 76.901,45.654 78.039,45.654 78.74,46.355 R31.1@90.944,46.355 90.932,46.367 v1(90.932,47.625)
  Bottom Layer w0.254: P2.3@22.352,74.422 23.622,75.692 23.622,77.47 24.511,78.359 35.433,78.359 44.704,69.088 86.614,69.088 90.944,64.758 90.932,64.746 v1(90.932,47.625)
nCONFIG: P2.5 R32.1 U5.14 | length 61.8
  Component Side w0.254: P2.5@24.892,74.422 23.622,75.692 23.622,77.597 24.765,78.74 34.417,78.74 35.722,77.435 35.722,57.94 44.819,48.843 R32.1@44.819,46.228 v1(45.974,46.228) ; v1(50.927,46.736) 51.689,46.736 52.203,47.25 U5.14@54.45,47.25
  Bottom Layer w0.254: v1(45.974,46.228) 49.403,46.228 49.911,46.736 v1(50.927,46.736)
nCS: P2.8 U5.8 U6.1 | length 59.7
  Component Side w0.254: P2.8@27.432,76.962 26.162,75.692 26.162,73.406 34.106,65.462 34.106,54.299 33.424,53.617 29.868,53.617 v1(29.337,53.086) U6.1@29.337,51.381 ; v1(48.641,51.562) 49.784,51.562 51.096,50.25 U5.8@54.45,50.25
  Bottom Layer w0.254: v1(29.337,53.086) 30.861,51.562 v1(48.641,51.562)
NetC8_1: C8.1 C12.1 C13.1 L2.1 U2.3 | length 7.5
  Component Side w0.508: U2.3@19.939,12.9 19.939,10.84 C13.1@20.574,10.205 C12.1@22.098,10.205 C8.1@23.622,10.205 23.634,10.217 L2.1@23.634,11.684
NetC15_1: C15.1 C18.1 C20.2 U1.5 U1.6 | length 6.6
  Component Side w0.254: C15.1@31.992,12.119 32.836,12.119 33.048,12.331 U1.6@33.77,12.331 U1.5@33.77,12.831
  Component Side w0.508: C20.2@28.448,10.84 28.448,11.557 29.01,12.119 C18.1@30.214,12.119 C15.1@31.738,12.119
NetC15_2: C15.2 C18.2 C19.2 U1.3 U1.4 | length 9.1
  Component Side w0.254: C15.2@31.992,13.479 32.836,13.479 32.984,13.331 U1.4@33.77,13.331 U1.3@33.77,13.831
  Component Side w0.508: C19.2@26.924,10.84 26.924,12.319 28.084,13.479 C18.2@30.214,13.479 C15.2@31.738,13.479
NetC16_2: C16.2 P10.1 R6.1 R9.2 | length 9.8
  Component Side w0.22: P10.1@4.445,17.526 10.91,17.526 R9.2@10.922,17.514 10.992,17.444 C16.2@12.446,17.444 12.491,17.399 R6.1@14.236,17.399
NetC17_2: C17.2 R2.1 R3.1 R10.2 U2.2 | length 14.3
  Component Side w0.508: U2.2@18.669,12.9 v1(18.669,14.351) ; v1(22.733,18.161) R2.1@23.888,18.161 R3.1@23.888,19.812 R10.2@23.888,21.463
  Bottom Layer w0.508: v1(18.669,14.351) 17.825,15.195 C17.2@17.825,15.24 17.825,17.063 18.923,18.161 v1(22.733,18.161)
NetC27_2: C27.2 D3.2 F1.2 L4.1 | length 5.4
  Component Side w1.016: L4.1@116.713,12.585 118.491,12.585 120.015,12.585 121.991,12.585 F1.2@122.047,12.641
NetC33_2: C33.2 U3.37 | length 2.2
  Component Side w0.254: C33.2@99.668,15.34 100.952,15.34 U3.37@101.579,15.966
NetC41_2: C41.2 R25.1 R26.2 U5.23 | length 70.3
  Component Side w0.254: v1(50.927,26.162) v1(50.927,31.75) ; v1(50.927,43.18) 51.816,43.18 52.246,42.75 U5.23@54.45,42.75 ; C41.2@92.202,18.46 92.272,18.53 R26.2@93.853,18.53 R25.1@95.504,18.53
  Component Side w0.508: C41.2@92.202,18.46 v1(92.202,19.558)
  Bottom Layer w0.254: v1(50.927,26.162) 87.503,26.162 92.202,21.463 v1(92.202,19.558) ; v1(50.927,31.75) v1(50.927,43.18)
NetC140_2: C140.2 C141.2 C142.2 L8.2 U11.2 U11.3 U11.4 | length 13.1
  Component Side w0.254: U11.4@13.347,27.485 13.347,28.744 13.663,29.06 13.847,29.06 13.947,29.06 14.023,29.06 14.347,28.736 U11.2@14.347,27.485 ; U11.3@13.847,27.485 C142.2@13.847,28.96
  Component Side w0.508: C142.2@13.843,29.165 13.847,29.161 13.847,29.06 C142.2@13.847,28.96
  Component Side w1.016: C142.2@13.947,29.06 13.97,29.083 L8.2@21.569,29.083
NetD4_1: D4.1 R23.1 | length 1.8
  Component Side w0.254: R23.1@118.352,10.414 D4.1@120.154,10.414
NetD5_1: D5.1 R24.1 | length 1.7
  Component Side w0.508: D5.1@93.599,22.249 93.611,22.237 R24.1@95.25,22.237
NetD6_1: D6.1 R62.2 | length 1.7
  Component Side w0.254: D6.1@62.535,19.902 R62.2@62.535,21.577
NetD7_1: D7.1 R63.2 | length 1.7
  Component Side w0.254: D7.1@64.186,19.902 R63.2@64.186,21.577
NetD8_1: D8.1 R64.2 | length 1.7
  Component Side w0.254: D8.1@65.837,19.902 R64.2@65.837,21.577
NetD9_1: D9.1 R65.2 | length 1.7
  Component Side w0.254: D9.1@67.488,19.902 R65.2@67.488,21.577
NetD10_1: D10.1 J1.2 | length 4.3
  Component Side w1.016: J1.2@101.854,71.755 D10.1@101.854,76.082
NetD11_1: D11.1 D14.1 F3.2 | length 6.9
  Component Side w1.016: F3.2@105.791,80.704 106.544,81.457 D11.1@106.544,83.82 D14.1@106.544,87.249
NetD13_1: D13.1 R85.1 | length 1.9
  Component Side w0.254: R85.1@97.143,73.152 97.143,75.057 D13.1@97.155,75.069
NetD15_1: D15.1 R87.1 | length 1.8
  Component Side w0.254: R87.1@73.914,79.236 D15.1@73.914,81.038
NetD16_1: D16.1 R88.1 | length 1.8
  Component Side w0.254: R88.1@47.105,71.755 D16.1@48.907,71.755
NetD16_2: D16.2 Q1.3 | length 1.7
  Component Side w0.254: D16.2@50.407,71.755 Q1.3@52.113,71.755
